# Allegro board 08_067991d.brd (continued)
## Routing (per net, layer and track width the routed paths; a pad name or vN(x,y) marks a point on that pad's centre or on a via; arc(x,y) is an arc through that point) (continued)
UNNAMED_2_AD243XW_I16_SWN: length 5.8
  TOP w0.254: R19.1 52.47,51.82 51.31,50.66 48.63,50.66 48.48,50.82 U11.39
UNNAMED_2_AD243XW_I16_SYNC: length 5.2
  TOP w0.178: R9.2 42.42,59.98 43.82,58.58 43.82,56.98 43.7,56.86 U11.8
UNNAMED_2_AD243XW_I16_VIN: length 7.5
  TOP w0.254: U11.46 48.98,54.32 v1(49.28,54.61)
  TOP w0.635: v1(49.28,54.61) 49.66,54.99 E3.2
  BOTTOM w0.305: v1(49.28,54.61) 49.24,54.61 48.48,53.85 48.25,53.85 C6.1
  BOTTOM w0.508: C7.1 v1(49.28,54.61)
UNNAMED_2_CAP_I61_N1: length 14.8
  TOP w0.508: R24.1 v1(58.29,60.8) ; v1(58.29,59.53) R27.1 ; v1(64.13,63.74) R22.1
  L3_PWR w0.508: v1(58.29,59.53) v1(58.29,60.8) 61.23,63.74 v1(64.13,63.74) 64.45,63.42 65.58,63.42 v1(66.93,64.77) v1(67.56,64.77)
UNNAMED_2_CN18PODDEVEN_I182_N1: length 2.6
  TOP w0.178: P2.1 E1.1
UNNAMED_2_CN18PODDEVEN_I182_N2: length 2.2
  TOP w0.178: P2.3 R1.1
UNNAMED_2_CN18PODDEVEN_I182_N3: length 2.2
  TOP w0.178: P2.5 R2.1
UNNAMED_2_CN18PODDEVEN_I182_N4: length 2.2
  TOP w0.178: P2.7 R3.1
UNNAMED_2_CN18PODDEVEN_I182_N5: length 2.2
  TOP w0.178: P2.9 R4.1
UNNAMED_2_CN18PODDEVEN_I182_N6: length 2.2
  TOP w0.178: P2.11 R5.1
UNNAMED_2_CN18PODDEVEN_I182_N7: length 2.2
  TOP w0.178: P2.13 R6.1
UNNAMED_2_CN18PODDEVEN_I182_N8: length 2.2
  TOP w0.178: P2.15 R7.1
UNNAMED_2_CN18PODDEVEN_I182_N9: length 2.2
  TOP w0.178: P2.17 R8.1
UNNAMED_2_DIOLED_I1_P: length 1.5
  TOP w0.178: R95.2 DS6.A
UNNAMED_2_DIOLED_I49_P: length 1.5
  TOP w0.178: R20.2 DS2.A
UNNAMED_2_DIOLED_I74_P: length 2.3
  TOP w0.178: DS3.A R21.2
UNNAMED_2_ICM24512_I59_E0: length 2.8
  TOP w0.178: R23.1 R22.2 U14.1
UNNAMED_2_ICM24512_I59_E1: length 3.5
  TOP w0.178: U14.2 R24.2 R25.1
UNNAMED_2_ICM24512_I59_E2: length 3.4
  TOP w0.178: R28.1 R27.2 U14.3
UNNAMED_2_ICM24512_I59_SCL: length 18
  TOP w0.178: S1.1B v1(79.25,55.13) ; U14.6 v1(65.89,59.53)
  BOTTOM w0.178: v1(79.25,55.13) 76.06,55.13 73.91,57.28 68.14,57.28 v1(65.89,59.53)
UNNAMED_2_ICM24512_I59_SDA: length 18.5
  TOP w0.178: U14.5 v1(65.89,58.26) ; S1.3B v1(79.25,52.59)
  BOTTOM w0.178: v1(65.89,58.26) 68.27,55.88 73.15,55.88 76.44,52.59 v1(79.25,52.59)
UNNAMED_2_NCTESTPAD_I202_N1: length 1.8
  TOP w0.178: TP10.1 R87.2
UNNAMED_3_ADLT8606V2_I35_BST: length 1.5
  TOP w0.254: C114.1 81.8,38.74 U8.1
UNNAMED_3_ADLT8606V2_I35_INTVCC: length 5.5
  TOP w0.203: U8.5 v1(84.33,40.18) ; U8.3 82.8,39.41 83.06,39.16 83.06,38.65 C53.1 v1(84.33,38.27)
  BOTTOM w0.254: v1(84.33,40.18) v1(84.33,38.27)
UNNAMED_3_ADLT8606V2_I35_PG: length 2
  TOP w0.203: U8.8 82.8,45.47 R110.2
UNNAMED_3_ADLT8606V2_I35_RT: length 3
  TOP w0.203: R107.2 84.57,39.24 83.57,39.24 83.3,39.5 U8.4
UNNAMED_3_ADLT8606V2_I35_SW: length 4.9
  TOP w0.254: U8.2 82.3,39.3 82.45,39.16 82.45,37.92 82.25,37.73 C114.2
  TOP w0.508: C114.2 79.93,37.73 L14.1
UNNAMED_3_ADLT8606V2_I35_TR: length 3.7
  TOP w0.203: C82.1 84.2,45.84 84.2,45.67 84,45.47 83.57,45.47 83.3,45.2 U8.7
UNNAMED_3_CAP_I7_N1: length 3.4
  TOP w0.241: FL1.1 32.65,30.88 32.65,31.74 C18.1 32.65,32.21 32.65,33.01 32.82,33.18 L1.2
UNNAMED_3_CAP_I8_N1: length 3.4
  TOP w0.241: FL1.2 32.24,30.88 32.24,31.74 C19.1 32.24,32.21 32.24,33.01 32.07,33.18 L2.2
UNNAMED_3_CAP_I12_N1: length 9
  TOP w0.178: R29.2 C20.2 v1(34.93,26.38) ; R30.1 C21.1 v1(29.96,26.38)
  BOTTOM w0.178: v1(29.96,26.38) 30.13,26.22 34.77,26.22 v1(34.93,26.38)
UNNAMED_3_CAP_I14_N1: length 4.5
  TOP w0.241: 32.24,25.16 32.24,24.71 C23.1 ; 32.24,25.16 R30.2 32.24,25.71 ; 32.24,25.16 32.24,25.71 ; FL1.3 32.24,27.23 32.24,25.71
UNNAMED_3_CAP_I14_N2: length 10.4
  TOP w0.241: P1.3 31.81,17.78 32.22,18.19 32.22,21.99 C23.2
  BOTTOM w0.965: L8.1 29.62,20.71 30.59,19.75 P1.3
UNNAMED_3_CAP_I15_N1: length 4.5
  TOP w0.241: 32.65,25.71 32.65,27.23 FL1.4 ; 32.65,25.71 32.65,25.16 ; 32.65,25.71 R29.1 32.65,25.16 ; 32.65,25.16 32.65,24.71 C22.1
UNNAMED_3_CAP_I15_N2: length 10.5
  TOP w0.241: P1.2 33.11,17.78 32.63,18.27 32.63,21.95 C22.2
  BOTTOM w0.965: L7.1 35.36,20.71 34.4,19.75 P1.2
UNNAMED_3_CAP_I32_N2: length 10.7
  BOTTOM w0.762: C123.2 24,14.35 25.65,12.7 P1.GND
UNNAMED_3_DIOLED_I23_P: length 18.5
  TOP w0.508: DS4.C v1(24.96,2) ; v1(41.85,2) DS8.A
  BOTTOM w0.508: v1(24.96,2) v1(41.85,2)
UNNAMED_3_DIOLED_I24_P: length 23.4
  TOP w0.508: DS4.A v1(21.53,2)
  BOTTOM w0.508: v1(21.53,2) 19.3,2 19.05,2.25 19.05,21.79 R91.1
UNNAMED_3_RES_I45_N2: length 3.3
  TOP w0.203: U8.6 83.8,44.81 83.95,44.96 85.1,44.96 R109.2 R108.2
UNNAMED_4_ADMAX17612X_I50_FLAGN: length 2.5
  TOP w0.203: R115.2 79.01,24.03 v1(79.01,24.26) U10.6
  BOTTOM w0.178: R117.1 79.01,23.9 v1(79.01,24.26)
UNNAMED_4_ADMAX17612X_I50_OVLO: length 5
  TOP w0.203: R113.1 77.34,29.55 77.54,29.76 79.54,29.76 79.75,29.55 R114.2 79.75,28.96 80.01,28.69 U10.3
UNNAMED_4_ADMAX17612X_I50_SETI: length 3.5
  TOP w0.203: U10.8 80.01,24.26 79.25,23.49 79.25,22.61 78.99,22.35 R116.2
UNNAMED_4_ADMAX17612X_I50_UVLO: length 6.8
  TOP w0.203: R111.1 77.34,31.04 77.54,31.24 79.54,31.24 79.75,31.04 R112.2 79.75,30.43 80.42,29.76 80.42,28.17 80.51,28.07 U10.2
UNNAMED_4_CAP_I2_N1: length 3.4
  TOP w0.241: FL2.2 56.75,30.88 56.75,31.74 C26.1 56.75,32.21 56.75,33.01 56.58,33.18 L3.2
UNNAMED_4_CAP_I3_N1: length 3.4
  TOP w0.241: L4.2 57.33,33.18 57.16,33.01 57.16,32.21 C27.1 57.16,31.74 57.16,30.88 FL2.1
UNNAMED_4_CAP_I12_N1: length 9
  TOP w0.178: v1(54.47,26.38) C28.2 R31.2 ; R32.1 C29.1 v1(59.44,26.38)
  BOTTOM w0.178: v1(54.47,26.38) 54.64,26.22 59.28,26.22 v1(59.44,26.38)
UNNAMED_4_CAP_I14_N1: length 4.5
  TOP w0.241: 57.16,25.16 57.16,25.71 ; 57.16,25.16 R32.2 57.16,25.71 ; 57.16,25.16 57.16,24.72 C24.1 ; 57.16,25.71 57.16,27.23 FL2.4
UNNAMED_4_CAP_I14_N2: length 14.1
  TOP w0.241: C24.2 57.16,21.96 57.16,16.13 57.62,15.67 58.63,15.67 58.88,15.92 P13.3
  BOTTOM w0.965: L12.1 60.51,18.78 P13.3
UNNAMED_4_CAP_I16_N1: length 4.5
  TOP w0.241: 56.75,25.71 56.75,27.23 FL2.3 ; 56.75,25.71 R31.1 56.75,25.16 ; 56.75,25.71 56.75,25.16 ; 56.75,25.16 56.75,24.7 C30.1
UNNAMED_4_CAP_I16_N2: length 18.2
  TOP w0.241: P13.2 56.75,15.01 56.75,21.98 C30.2
  BOTTOM w0.965: L11.1 53.4,15.01 P13.2
UNNAMED_4_DIOLED_I30_P: length 18.5
  TOP w0.508: DS9.C v1(69.85,2) ; v1(53.28,2) DS12.A
  BOTTOM w0.508: v1(69.85,2) v1(53.28,2)
UNNAMED_4_DIOLED_I31_P: length 24
  TOP w0.508: DS9.A v1(73.53,2)
  BOTTOM w0.508: v1(73.53,2) 73.15,2 72.64,2.51 72.64,20.57 71.3,21.92 R36.1
UNNAMED_4_DIOSCHOTTKY_I34_N: length 19.8
  TOP w0.254: U10.10 81.01,23.88
  TOP w1.016: 81.01,23.88 81.01,22.91 C117.2 80.96,21.59 79.31,19.94 75.18,19.94 73.79,21.34 TP11.1
  BOTTOM w0.508: TP11.1 R36.2
UNNAMED_4_RES_I22_N2: length 1.8
  BOTTOM w0.508: Q1.4 63.13,27.36 R33.2
UNNAMED_5_CAP_I15_N1: length 70.1
  TOP w0.178: E5.1 C37.2 v1(56.72,46.43) ; C39.1 v1(42.25,29.11) ; C36.2 v1(42.25,40.66) ; C38.2 v1(32.25,46.43)
  BOTTOM w0.178: v1(56.72,46.43) 55.93,46.43 55.83,46.53 v1(55.29,46.53) 54.43,46.53 v1(53.61,45.71) 53.98,45.35 53.98,43.56 49.91,39.5 49.91,36.71 46.86,33.67 46.86,29.97 46.1,29.21 v1(45.29,29.21) 44.58,29.21 43.76,28.39 v1(43.61,28.39) 42.98,28.39 v1(42.25,29.11) 42.25,30.82 47.05,35.62 47.05,38.54 46.74,38.86 45.62,38.86 44.1,37.34 43.05,37.34 42.67,37.72 42.67,39 v1(43.61,39.94) 42.89,40.66 v1(42.25,40.66) 38.08,40.66 36.32,42.42 33.02,42.42 31.5,43.94 31.5,46.1 31.83,46.43 v1(32.25,46.43) 32.89,46.43 v1(33.61,45.71)
UNNAMED_5_ICT3902_I1_DATA: length 2.8
  TOP w0.178: R40.1 v1(44,38.55)
  BOTTOM w0.178: v1(45.29,39.94) 44,38.65 v1(44,38.55)
UNNAMED_5_ICT3902_I2_DATA: length 3
  TOP w0.178: v1(44,27.13) R39.1
  BOTTOM w0.178: v1(45.29,28.39) 45.29,27.63 44.79,27.13 v1(44,27.13)
UNNAMED_5_ICT3902_I3_DATA: length 4.4
  TOP w0.178: v1(32.77,44.32) R38.1
  BOTTOM w0.203: v1(35.29,45.71) 35.29,45.07 34.8,44.58 33.02,44.58 v1(32.77,44.32)
UNNAMED_5_ICT3902_I4_DATA: length 2.6
  TOP w0.178: R37.1 v1(56.65,44.96)
  BOTTOM w0.178: v1(55.29,45.71) 56.04,44.96 v1(56.65,44.96)
UNNAMED_7_AD8606_I11_INV: length 10.9
  TOP w0.178: C52.P 17.5,66.27 18.61,67.37 18.61,72.58 C46.2 18.67,73.01 18.67,73.4 U7.A1 U7.B1
UNNAMED_7_AD8606_I11_NINV: length 2.4
  TOP w0.178: U7.C1 20.18,73.01 C44.1 20.42,72.75 R44.2
UNNAMED_7_AD8606_I21_INV: length 9
  TOP w0.178: U7.B3 U7.A3 18.85,74.91 18.67,75.09 18.67,75.82 C45.2 18.61,76.25 18.61,79.31 17.49,80.42 C51.P
UNNAMED_7_AD8606_I21_NINV: length 2.4
  TOP w0.178: U7.C3 20.18,75.81 C43.1 20.42,76.08 R43.2
UNNAMED_7_AD8606_I58_INV: length 10.9
  TOP w0.178: C62.P 17.5,89.13 18.61,90.23 18.61,95.44 C60.2 18.67,95.87 18.67,96.26 U9.A1 U9.B1
UNNAMED_7_AD8606_I58_NINV: length 2.4
  TOP w0.178: U9.C1 20.18,95.87 C58.1 20.42,95.61 R54.2
UNNAMED_7_AD8606_I66_INV: length 9
  TOP w0.178: U9.B3 U9.A3 18.85,97.77 18.67,97.95 18.67,98.68 C59.2 18.61,99.11 18.61,102.17 17.49,103.28 C61.P
UNNAMED_7_AD8606_I66_NINV: length 2.4
  TOP w0.178: U9.C3 20.18,98.67 C57.1 20.42,98.94 R53.2
UNNAMED_7_CAP_I20_N1: length 2.3
  TOP w0.178: R42.2 R44.1 C46.1
UNNAMED_7_CAP_I22_N1: length 2.3
  TOP w0.178: R41.2 R43.1 C45.1
UNNAMED_7_CAP_I29_N1: length 7.9
  TOP w0.178: C48.1 11.44,113.4 12.32,112.52 C50.2
  TOP w0.203: C48.1 E10.2
UNNAMED_7_CAP_I34_N1: length 9.1
  TOP w0.203: C49.2 13.58,128.75 12.33,127.51 12.33,126.24 11.29,125.19 C47.1 E9.2
UNNAMED_7_CAP_I38_N1: length 11.3
  TOP w0.178: R48.2 C55.1 R50.1 6.44,69.47 7.69,70.71 P6.2
UNNAMED_7_CAP_I46_N1: length 6.3
  TOP w0.178: P6.3 4.4,80 4.82,80.42 R49.1 C54.1 R47.2
UNNAMED_7_CAP_I60_N1: length 11.3
  TOP w0.178: P7.2 7.69,93.57 6.44,92.33 R58.1 C65.1 R56.2
UNNAMED_7_CAP_I64_N1: length 2.3
  TOP w0.178: C60.1 R54.1 R52.2
UNNAMED_7_CAP_I67_N1: length 2.3
  TOP w0.178: C59.1 R53.1 R51.2
UNNAMED_7_CAP_I73_N1: length 6.3
  TOP w0.178: R55.2 C64.1 R57.1 4.82,103.28 4.4,102.86 P7.3
UNNAMED_7_CAP_I83_N1: length 3.5
  TOP w0.178: R45.1 23.44,128.19 22.89,128.75 C49.1
UNNAMED_7_CAP_I84_N1: length 3.4
  TOP w0.178: R46.1 23.44,113.23 22.73,112.52 C50.1
UNNAMED_7_CAPP_I23_N2: length 2.4
  TOP w0.178: R48.1 C52.N
UNNAMED_7_CAPP_I25_N2: length 2.5
  TOP w0.178: R47.1 C51.N
UNNAMED_7_CAPP_I68_N2: length 2.4
  TOP w0.178: R56.1 C62.N
UNNAMED_7_CAPP_I69_N2: length 2.5
  TOP w0.178: R55.1 C61.N
UNNAMED_7_CN3P_I18_N2: length 2.9
  TOP w0.203: E10.1 9.86,116.94 P4.2
UNNAMED_7_CN3P_I18_N3: length 2.9
  TOP w0.203: P4.3 5.26,125.19 E9.1
UNNAMED_10_CAP_I3_N1: length 11.4
  TOP w1.016: L5.2 C75.1 P16.1
UNNAMED_10_CAP_I5_N1: length 1.3
  TOP w0.508: 44.07,113.6 45.32,113.6 C68.1
UNNAMED_10_CAP_I7_N1: length 1.5
  TOP w0.508: R61.2 C69.1
UNNAMED_10_CAP_I9_N2: length 11.4
  TOP w1.016: P17.1 C76.2 L6.2
UNNAMED_10_CAP_I12_N1: length 4.7
  TOP w0.254: U16.16 52.07,119.48 53.21,120.61 C79.1
UNNAMED_10_CAP_I14_N1: length 11.4
  TOP w1.016: L9.2 C77.1 P18.1
UNNAMED_10_CAP_I15_N2: length 11.4
  TOP w1.016: P19.1 C78.2 L10.2
UNNAMED_10_CAP_I19_N2: length 4.6
  TOP w0.254: 49.4,115.74 U16.19
  TOP w0.508: C70.2 47.86,115.74 49.4,115.74
  TOP w0.635: C70.2 R61.1
UNNAMED_10_CAP_I21_N1: length 2.8
  TOP w0.254: U16.22 48.42,114.24 C31.1
UNNAMED_10_CAP_I21_N2: length 10.2
  TOP w0.254: U16.23 50.05,113.74 49.74,113.43 49.74,112.65
  TOP w0.406: 49.74,112.65 49.4,112.31 49.4,111.52 48.72,110.84 C31.2
  TOP w0.508: C31.2 45.03,110.84 L5.1 ; C68.2 45.34,111.38
UNNAMED_10_CAP_I24_N2: length 5
  TOP w0.254: C73.2 51.18,120.78 51.57,120.38 U16.17
UNNAMED_10_CAP_I25_N1: length 1.4
  TOP w0.508: R62.2 C71.1
UNNAMED_10_CAP_I26_N2: length 3.2
  TOP w0.254: 54.99,115.74 U16.12
  TOP w0.508: C67.2 56.97,115.74 54.99,115.74
UNNAMED_10_CAP_I29_N1: length 10.6
  TOP w0.254: L10.1 61.09,109.34 R76.1 57.66,110.61 C34.1 ; 55.05,113.54 54.85,113.74 U16.8
  TOP w0.508: C34.1 56.52,110.99 55.24,112.27 55.24,113.34 55.05,113.54
UNNAMED_10_CAP_I29_N2: length 3.2
  TOP w0.178: 55.37,114.22 55.36,114.24 U16.9
  TOP w0.508: 55.37,114.22 56.91,114.22 C34.2
UNNAMED_10_CAP_I39_N1: length 1.3
  TOP w0.508: C72.1 R76.2
UNNAMED_10_CAP_I55_N1: length 3.3
  TOP w0.178: U16.6 53.57,112.23 v1(53.95,111.86)
  BOTTOM w0.178: R99.2 C118.1 54.36,111.45 v1(53.95,111.86)
UNNAMED_10_CN3P_I53_N2: length 13
  TOP w0.178: R63.2 48.77,106.3 50.04,107.57 53.06,107.57 53.98,108.49 53.98,111.06 53.07,111.96 U16.5
  TOP w0.254: R63.2 JP2.2
UNNAMED_10_CN3P_I54_N1: length 2.3
  TOP w0.254: R65.2 54.74,106.15 JP3.1
UNNAMED_10_CN3P_I54_N2: length 5.8
  TOP w0.178: R66.1 55.47,108.34 57.28,106.53 JP3.2
UNNAMED_10_DIOLED_I30_N: length 15.2
  TOP w0.178: DS11.C 47.5,99.42 47.5,107.44 50.04,109.98 50.13,110.07 50.13,111.99 50.44,112.31 U16.24
UNNAMED_10_DIOLED_I30_P: length 1.5
  TOP w0.178: DS11.A R64.2
UNNAMED_10_ICBD28623MUV_I28_BCLK: length 1.9
  TOP w0.178: R68.2 U16.3
UNNAMED_10_ICBD28623MUV_I28_LRCLK: length 2.1
  TOP w0.178: R59.2 52.57,111.36 U16.4
UNNAMED_10_ICBD28623MUV_I28_MUTEX: length 4.2
  TOP w0.178: R66.2 54.49,109.71 54.49,113.06 54.32,113.24 U16.7
UNNAMED_10_ICBD28623MUV_I28_SDATA: length 2.1
  TOP w0.178: U16.2 51.57,111.37 R67.2
UNNAMED_11_ADAU1701_I48_ADCRES: length 2
  TOP w0.178: U12.3 R69.2
UNNAMED_11_ADAU1701_I48_CM: length 2.9
  TOP w0.254: U12.40 39.39,83.03 C89.1 C91.1
UNNAMED_11_ADAU1701_I48_DVDD: length 4.8
  TOP w0.254: C96.1 50.61,84.53 U12.24 ; U12.13 C94.1
  TOP w0.508: C94.1 v1(51.55,79.03) ; C96.1 v1(51.55,84.72)
  vias: v1(51.18,74.92) v1(51.18,74.41) v1(51.18,73.9) v1(51.69,74.92) v1(51.69,74.41) v1(51.69,73.9) v1(54.86,83.44) v1(55.37,83.44)
UNNAMED_11_ADAU1701_I48_FILTA: length 3.9
  TOP w0.178: v1(38.99,79.38) 39.14,79.53 U12.47
  BOTTOM w0.178: C85.1 C87.1 39,79.38 v1(38.99,79.38)
UNNAMED_11_ADAU1701_I48_FILTD: length 2.9
  TOP w0.254: C98.1 C99.1 39.36,82.53 U12.41
UNNAMED_11_ADAU1701_I48_MP6: length 3.9
  TOP w0.178: R70.2 51.81,80.52 50.55,80.52 50.06,80.03 U12.15
UNNAMED_11_ADAU1701_I48_PLLLF: length 4.8
  TOP w0.178: U12.35 C97.1 C95.1
UNNAMED_11_ADAU1701_I48_RESETB: length 21.3
  TOP w0.178: U12.5 44.24,76.61 44.2,76.56 44.2,75.04 44.44,74.8 45.12,74.8 45.3,74.61 C80.2 45.3,72.82 R98.1 45.6,71.87 45.83,71.64 49.03,71.64 49.53,72.14 56.26,72.14 56.77,71.63 56.77,70.87 57.53,70.1 R88.1
UNNAMED_11_ADAU1701_I48_SELFBOOT: length 9.9
  TOP w0.178: U12.6 v1(44.74,75.69) ; R73.1 P9.1
  BOTTOM w0.178: v1(44.74,75.69) 42.46,73.41 P9.1
UNNAMED_11_ADAU1701_I48_VDRIVE: length 5.4
  TOP w0.254: U12.17 R72.1 53.19,81.03 Q2.1
UNNAMED_11_CAP_I20_N2: length 1
  TOP w0.178: R71.1 C95.2
UNNAMED_11_CAP_I41_N2: length 2.8
  TOP w0.508: E11.2 C100.2 U15.8
UNNAMED_11_CN10P_I109_N4: length 4.6
  TOP w0.178: DS5.A 67.56,93.68 P10.4
UNNAMED_11_DIOLED_I121_N: length 2.2
  TOP w0.178: R77.1 DS5.C
UNNAMED_11_ICM24512_I37_SCL: length 2
  TOP w0.178: U15.6 R74.1
UNNAMED_11_ICM24512_I37_SDA: length 2
  TOP w0.178: U15.5 R75.1
UNNAMED_11_NCTESTPAD_I134_N1: length 1.8
  TOP w0.178: TP12.1 R88.2
UNNAMED_12_ADLT8609_I124_BST: length 2.2
  TOP w0.178: C105.2 15.49,51.44 15.31,51.27 U5.1
UNNAMED_12_ADLT8609_I124_EN: length 2.8
  TOP w0.178: R80.1 R79.1 15.22,45.92 14.72,46.42 U5.10
UNNAMED_12_ADLT8609_I124_FB: length 4
  TOP w0.178: R84.2 C107.2 R85.2 11.84,46.74 12.15,47.05 U5.6
UNNAMED_12_ADLT8609_I124_INTVCC: length 5.3
  TOP w0.178: 10.15,52.27 10.13,52.27 C103.1 9.84,52.58 10.15,52.27 ; 10.15,52.27 R81.1 13.39,52.27 13.72,51.94 U5.3
UNNAMED_12_ADLT8609_I124_PG: length 4.5
  TOP w0.178: R83.2 12.32,43.94 13.46,45.09 13.46,45.85 13.72,46.1 U5.8
UNNAMED_12_ADLT8609_I124_RT: length 4.5
  TOP w0.178: R82.1 10.15,50.58 10.33,50.4 13.04,50.4 13.22,50.58 U5.4
UNNAMED_12_ADLT8609_I124_SYNC: length 1.5
  TOP w0.178: U5.5 R81.2
UNNAMED_12_ADLT8609_I124_TR: length 2.6
  TOP w0.178: C104.2 12.42,45.34 13.22,46.14 U5.7
UNNAMED_12_ADLT8609_I124_VIN: length 2.9
  TOP w0.508: E14.1 12.23,37.07 R151.1
UNNAMED_12_CAP_I111_N1: length 14.5
  TOP w0.508: C107.1 v1(8.28,46.74) ; R84.1 v1(8.28,47.88)
  BOTTOM w0.508: v1(8.28,46.74) v1(8.28,47.88) 11.81,51.41 v1(11.81,57.66) v1(11.81,58.29)
UNNAMED_12_DIOLED_I105_P: length 1.5
  TOP w0.508: DS1.A R16.2
UNNAMED_12_DIOLED_I136_P: length 1.7
  TOP w0.508: DS10.A R151.2
VOUT0: length 21.1
  TOP w0.178: R41.1 25.91,78.36 27.54,79.99 40.24,79.99 40.28,80.03 U12.46
VOUT1: length 27.6
  TOP w0.178: R42.1 28.32,70.48 34.04,76.2 39.24,76.2 41.91,78.87 41.91,80.39 41.77,80.53 U12.45
VOUT2: length 46.9
  TOP w0.178: R51.1 v1(21.21,101.22) ; v1(42.93,81.28) 42.67,81.03 U12.44
  BOTTOM w0.178: v1(42.93,81.28) 42.58,80.94 41.74,80.94 41.27,81.41 37.85,81.41 37.21,80.77 21.46,80.77 19.69,82.55 19.69,99.69 v1(21.21,101.22)
VOUT3: length 33.4
  TOP w0.178: R52.1 v1(21.21,93.34) ; v1(42.29,81.66) 42.29,81.66 42.16,81.53 U12.43
  BOTTOM w0.178: v1(21.21,93.34) 21.21,84.58 23.75,82.04 41.4,82.04 41.78,81.66 v1(42.29,81.66)
VSENSEP: length 40.5
  TOP w0.254: U11.40 48.63,51.32 48.78,51.17 50.4,51.17 v1(51.56,52.32)
  BOTTOM w0.406: v1(51.56,52.32) 59.94,52.32 69.22,43.05 69.22,28.61 R34.1

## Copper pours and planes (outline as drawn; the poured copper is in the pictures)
24V on TOP (solid shape): 71.89,30.98 71.89,27.06 71.2,26.37 67.68,26.37 67.68,31.96 70.91,31.96
24V on TOP (solid shape): 82.55,49.91 82.55,45.64 82.52,45.59 81.41,45.59 81.41,49.91 81.53,50.04 82.42,50.04
24V on TOP: 24.93,31.96 24.93,26.37 21.65,26.37 20.45,27.57 20.45,30.99 21.42,31.96
24V on BOTTOM: 66.73,34.47 66.73,35.87 69.22,35.87 69.22,34.01 67.76,34.01 67.76,34.47
24V on BOTTOM: 45.78,112.39 55.79,112.39 57.06,111.12 59.86,111.12 59.86,122.14 56.48,122.14 51.82,117.47 45.78,117.47
24V on BOTTOM: 39.15,25.93 23.37,25.93 22.49,26.81 18.04,26.81 17.91,26.67 17.91,24.07 25.39,24.07 25.74,23.72 39.15,23.72
24V on L4_PWR: 25.72,138.43 87.63,138.43 87.63,1.27 1.27,1.27 1.27,40.83 25.97,40.83 25.97,16.64 26.06,16.41 26.29,16.32 69.6,16.32 69.82,16.41 69.91,16.64 69.91,23.11 69.82,23.34 69.6,23.43 62.67,23.43 62.67,35.5 76.33,35.5 76.55,35.59 76.64,35.81 76.64,77.6 76.55,77.82 76.33,77.91 60.77,77.91 60.77,93.73 60.68,93.95 60.45,94.04 58.61,94.04 58.61,108.33 58.52,108.56 58.29,108.65 44.32,108.65 44.1,108.56 44.01,108.33 44.01,98.23 39.75,98.23 39.63,98.21 39.53,98.14 35.3,93.92 25.72,93.92 ; 3 cut-outs
DGND on TOP: 10.33,43.17 7.86,43.17 7.62,42.93 7.62,41.4 7.87,41.15 10.31,41.15 10.33,41.16
DGND on TOP: 1.27,138.43 87.63,138.43 87.63,1.27 1.27,1.27 ; 14 cut-outs
DGND on BOTTOM: 1.27,138.43 87.63,138.43 87.63,1.27 1.27,1.27 ; 17 cut-outs
DGND on L2_GND, L5_GND: 1.27,138.43 87.63,138.43 87.63,1.27 1.27,1.27 ; 4 cut-outs
DGND on L3_PWR: 1.27,138.43 87.63,138.43 87.63,1.27 1.27,1.27 ; 15 cut-outs
DGND on L4_PWR: 1.27,138.43 25.08,138.43 25.08,104.71 1.27,104.71 ; 1 cut-out
DGND on L4_PWR: 41.59,55.44 47.56,55.44 47.56,54.48 47.57,54.42 47.59,54.36 47.57,54.29 47.56,54.23 47.56,49.59 41.59,49.59
VDD_3V3 on TOP: 10.22,59.8 11.37,59.8 11.58,60.02 16.64,60.02 16.64,62.1 16,62.74 10.55,62.74 10.5,62.69 10.5,61.94 10.22,61.66
VDD_3V3 on TOP: 56.57,80.73 56.57,78.61 56.44,78.49 55.68,78.49 55.55,78.61 55.55,80.73
VDD_3V3 on TOP: 35.81,86.83 39.33,86.83 39.5,87 39.5,88.27 39.33,88.43 35.81,88.43
VDD_3V3 on BOTTOM: 66.04,21.33 66.04,19.81 67.95,19.81 68.07,19.94 68.07,21.21 67.95,21.33
VDD_3V3 on L4_PWR: 44.64,108.01 57.98,108.01 57.98,93.73 58.07,93.5 58.29,93.41 60.13,93.41 60.13,77.6 60.23,77.37 60.45,77.28 76.01,77.28 76.01,36.13 62.36,36.13 62.13,36.04 62.04,35.81 62.04,23.11 62.13,22.89 62.36,22.8 69.28,22.8 69.28,16.95 26.61,16.95 26.61,41.15 26.51,41.37 26.29,41.47 1.27,41.47 1.27,104.08 25.08,104.08 25.08,93.6 25.18,93.37 25.4,93.28 35.43,93.28 35.55,93.31 35.66,93.37 39.88,97.6 44.32,97.6 44.55,97.69 44.64,97.92 ; 1 cut-out
VDD_5V on TOP (solid shape): 78.05,33.1 77.85,32.89 76.58,32.89 76.33,33.15 76.33,39.32 76.58,39.57 78.05,39.57
VDD_5V on TOP: 81.79,29.72 81.46,29.72 81.28,29.54 81.28,28.52 81.13,28.37 80.9,28.37 80.72,28.55 80.72,30.78 80.82,30.89 81.84,30.89 81.94,30.78 81.94,29.87
VDD_5V on TOP: 53.67,54.46 55.17,54.46 55.27,54.56 55.27,55.4 55.17,55.5 53.67,55.5
(no net) on TOP: 67.68,31.96 67.68,26.37 71.2,26.37 71.89,27.06 71.89,30.98 70.91,31.96
(no net) on TOP: 78.05,39.57 76.58,39.57 76.33,39.32 76.33,33.15 76.58,32.89 77.85,32.89 78.05,33.1
(no net) on TOP: 80.85,37.41 80.42,36.98 80.42,35.86 79.43,35.86 79.43,39.57 80.42,39.57 80.42,38.43 80.82,38.02 82.12,38.02 82.32,38.23 82.32,39.4 82.4,39.4 82.73,39.07 82.73,37.72 82.42,37.41
(no net) on TOP: 82.55,45.59 82.55,49.91 82.42,50.04 81.53,50.04 81.41,49.91 81.41,45.59
AD243X_IOVDD on TOP: 54.62,88.43 51.09,88.43 50.93,88.27 50.93,87 51.09,86.83 54.62,86.83
AD243X_IOVDD on L3_PWR: 52.7,88.39 52.45,88.65 51.05,88.65 50.8,88.39 50.8,81.79 51.05,81.53 52.45,81.53 52.7,81.79
AD243X_IOVDD on L4_PWR: 45.47,88.96 52.26,88.96 52.26,86.8 46.99,86.8 46.77,86.71 46.67,86.49 46.67,73.28 46.77,73.05 46.99,72.96 54.17,72.96 54.17,65.09 42.67,65.09 42.45,64.99 42.35,64.77 42.35,60.71 42.45,60.48 42.67,60.39 44.13,60.39 44.13,56.07 41.27,56.07 41.05,55.98 40.96,55.75 40.96,49.59 30.54,49.59 30.54,63.18 33.59,63.18 33.59,60.71 33.68,60.48 33.91,60.39 36.32,60.39 36.55,60.48 36.64,60.71 36.64,71.06 43.81,71.06 44.04,71.15 44.13,71.37 44.13,73.79 44.11,73.91 44.04,74.01 43.12,74.93 43.12,86.61
AD243X_VOUT2 on TOP: 68.57,65.15 70.37,65.15 70.48,65.27 70.48,66.16 70.36,66.28 68.71,66.28 68.57,66.14
AD243X_VOUT2 on TOP: 45.34,44.43 45.47,44.83 45.38,45.32 45.38,45.68 45.02,46.04 45.02,47.46 44.85,47.63 44.85,49.01 44.55,49.01 44.55,47.63 44.39,47.47 44.39,46.04 43.93,45.59 43.93,45.07 43.81,44.83 44,44.43 44,43.63 44.2,43.43 45.21,43.43 45.34,43.56
AD243X_VOUT2 on L4_PWR: 42.99,64.45 55.69,64.45 55.69,43.24 41.59,43.24 41.59,48.96 47.88,48.96 48.1,49.05 48.2,49.28 48.2,54.17 53.47,54.17 53.69,54.26 53.78,54.48 53.78,60.71 53.69,60.93 53.47,61.02 42.99,61.02
ISENSEP on BOTTOM: 64.83,35.87 64.83,34.33 64.2,33.71 63.2,33.71 63.2,32.69 63.35,32.69 63.35,32.39 62.62,32.39 62.62,31.8 63.35,31.8 63.35,29.97 62.62,29.97 62.62,29.36 63.35,29.36 63.35,29.19 67.47,29.19 67.47,29.36 68.2,29.36 68.2,29.97 67.47,29.97 67.47,31.8 68.2,31.8 68.2,32.39 67.47,32.39 67.47,32.69 67.62,32.69 67.62,33.71 66.35,33.71 66.35,33.72 65.87,34.2 65.87,35.87
UNNAMED_2_AD243XW_I16_DVDD1 on L4_PWR: 44.77,60.39 53.15,60.39 53.15,54.8 48.2,54.8 48.2,55.75 48.1,55.98 47.88,56.07 44.77,56.07
UNNAMED_2_CAP_I61_N1 on TOP: 67.91,66.14 66.92,66.14 66.42,65.65 66.42,61.84 68.45,61.84 68.45,62.22 67.91,62.77
UNNAMED_3_ADLT8606V2_I35_SW on TOP (solid shape): 80.42,38.43 80.82,38.02 82.12,38.02 82.32,38.23 82.32,38.44 82.32,39.02 82.32,39.03 82.32,39.4 82.4,39.4 82.55,39.24 82.57,39.22 82.59,39.2 82.73,39.06 82.73,37.72 82.42,37.41 80.85,37.41 80.42,36.98 80.42,35.86 79.43,35.86 79.43,39.57 80.42,39.57
UNNAMED_4_DIOSCHOTTKY_I34_N on BOTTOM: 64.47,26.44 62.82,26.44 62.31,25.93 50.25,25.93 50.25,23.72 71.22,23.72 71.51,24 71.51,27.68 67.62,27.68 67.62,28.37 64.47,28.37
UNNAMED_4_DIOSCHOTTKY_I34_P on BOTTOM: 64.68,22.61 67.42,22.61 67.42,21.7 66.15,21.7 65.87,21.42 64.68,21.42
UNNAMED_10_CAP_I3_N1 on TOP: 32.83,94.83 38.57,100.57 37.65,103.69 35.18,105.81 35.18,106.92 35.81,107.56 37.21,107.56 37.21,111.5 33.02,111.5 32.18,110.66 32.18,107.52 30.48,105.81 28.01,103.69 27.09,100.57
UNNAMED_10_CAP_I9_N2 on TOP: 32.83,133 38.57,127.25 37.65,124.13 35.18,122.01 35.18,120.9 35.81,120.27 37.21,120.27 37.21,116.33 33.02,116.33 32.18,117.17 32.18,120.31 30.48,122.01 28.01,124.13 27.09,127.25
UNNAMED_10_CAP_I14_N1 on TOP: 73.09,133 67.35,127.25 68.27,124.13 70.74,122.01 70.74,120.9 70.1,120.27 68.71,120.27 68.71,116.33 72.9,116.33 73.74,117.17 73.74,120.31 75.44,122.01 77.91,124.13 78.83,127.25
UNNAMED_10_CAP_I15_N2 on TOP: 73.09,94.83 67.35,100.57 68.27,103.69 70.74,105.81 70.74,106.92 70.1,107.56 68.71,107.56 68.71,111.5 72.9,111.5 73.74,110.66 73.74,107.52 75.44,105.81 77.91,103.69 78.83,100.57
UNNAMED_10_CAP_I19_N1 on TOP: 46.85,118.28 48.47,118.28 50.04,116.71 50.04,116.14 51.21,116.14 51.21,118.08 49.87,119.42 46.85,119.42
UNNAMED_10_CAP_I19_N2 on TOP: 48.65,116.42 46.85,116.42 46.6,116.17 45,116.17 44.55,116.62 44.55,120.27 42.04,120.27 42.04,115.57 42.33,115.28 48.65,115.28
UNNAMED_10_CAP_I21_N2 on TOP: 42.52,107.94 42.52,111.48 42.8,111.76 49.28,111.76 49.28,110.11 45.59,110.11 44.55,109.06 44.55,107.94
UNNAMED_10_CAP_I25_N2 on TOP: 58.52,118.22 56.12,118.22 54.61,116.71 54.61,116.14 53.43,116.14 53.43,118.08 54.95,119.59 58.67,119.59 58.97,119.89 63.4,119.89 63.4,117.09 61.37,117.09 61.17,117.29 59.45,117.29
UNNAMED_10_CAP_I29_N1 on TOP: 63.4,110.73 60.72,110.73 60.52,110.93 58.99,110.93 58.24,111.68 55.88,111.68 55.88,109.6 57.54,107.94 63.4,107.94
UNNAMED_11_ADAU1701_I48_DVDD on TOP: 54.62,75.22 51.09,75.22 50.93,75.06 50.93,73.79 51.09,73.62 54.62,73.62
UNNAMED_11_ADAU1701_I48_DVDD on TOP: 54.61,81.57 54.61,83.69 54.74,83.82 55.5,83.82 55.63,83.69 55.63,81.57
UNNAMED_11_ADAU1701_I48_DVDD on L4_PWR: 47.31,86.17 56.45,86.17 56.45,83.12 50.16,83.12 49.94,83.03 49.85,82.8 49.85,79.76 49.94,79.53 50.16,79.44 54.17,79.44 54.17,73.6 47.31,73.6
UNNAMED_12_ADLT8609_I124_SW on TOP: 14.37,50.69 14.37,51.94 14.78,52.35 14.78,53.16 15.71,54.09 16.34,54.09 16.34,55.05 12.63,55.05 12.63,53.79 14.06,52.36 14.06,50.69
UNNAMED_12_ADLT8609_I124_VIN on TOP: 14.06,47.62 14.06,46 13.84,45.78 13.84,44.58 12.81,43.55 11.52,43.55 11.52,40.61 11.76,40.37 11.76,39.04 11.94,38.86 13.34,38.86 13.46,38.99 13.46,42.55 14.1,43.18 14.78,43.18 14.78,44.85 14.53,45.1 14.53,46.05 14.37,46.21 14.37,47.62
UNNAMED_12_CAP_I111_N1 on TOP: 12.63,56.45 16.34,56.45 16.34,57.42 14.45,57.42 13.45,58.42 13.45,59.36 12.46,59.36 12.29,59.19 10.22,59.19 9.99,58.97 9.99,55.63 11.81,55.63

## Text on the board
Ref Des/Silkscreen Bottom: A | C
User.Comments: SEE NOTE 6 | (4 PLACES) | 5.    U11 IS A DEVICE-SOCKET COMBO AND FOLLOWS THIS SOLDERPASTE INSTRUCTION: | 6.    BOARD ASSEMBLY SPECIAL NOTES: (IN ORDER TO MINIMIZE MIC DEVICES (U1-U4) DAMAGE) | 7.    BOARDS TO BE SHIPPED SINGULATED AFTER ASSEMBLY PROCESS. | SMOOTHEN EDGES AND FREE FROM BURRS AFTER DEPANELIZATION PROCESS. | A. DO NOT BOARD WASH OR CLEAN AFTER THE REFLOW PROCESS. | C. DO NOT DIRECTLY EXPOSE TO ULTRASONIC PROCESSING, WELDING, OR CLEANING. | E. DO NOT APPLY OVER 30 PSI OF AIR PRESSURE INTO THE PORT HOLE. | B. DO NOT BRUSH BOARD WITH OR WITHOUT SOLVENTS AFTER THE REFLOW PROCESS. | D. DO NOT INSERT ANY OBJECT IN PORT HOLE OF DEVICE AT ANY TIME. | F. DO NOT PULL A VACUUM OVER PORT HOLE OF THE MICROPHONE. | G. DO NOT APPLY A VACUUM WHEN REPACKING INTO SEALED BAGS AT A RATE | SUPPLIED PART | U11(DEVICE) | U11(SOCKET) | FASTER THAN 0.5 ATM/SEC. | INSTALLED SOCKET | INSTALLED PART | INSTALLED DUT | NO PASTEMASK | PASTEMASK
Ref Des/Assembly Top: 1 | C | A | MATE ENTRY | +
Ref Des/Silkscreen Top: 24V | C | A | 3V3 | GND | MISO | MOSI | SCK | SIO2 | ADR1 | MCLK | AD2437 SIO0 SEL | IRQ | MULTIPURPOSE | SPKR L | SPKR- | (MP 1,2,3,7,8,9) | 2 | MAX LOAD: | 8 OHMS | BOOT | DISABLE | PINS | PORT A | TOWARDS MAIN | ERROR | GAIN | EVAL-AD2437B1NZ | MUTE | RESET | SI02 | PORT B | TOWARDS SUB | I2C BUS SEL | SPKR R | SPKR R- | USBi | DAC1 OUT | DAC0 OUT | ADC IN | PDM_OUT2 | AD_DRX0 | ADA_DRX0 | I2S | CONNECTOR | BCLK | SYNC | SIO4 | SIO3 | MALE | SIO0 | SIO1 | PDM_CLK | FEMALE | +
PAGE_OUTLINE: B | C | D | CHANGES PER ECR-106613 | CHANGES PER ECR-110081 | CHANGES PER ECR-113667 | 21MAR22 | 29NOV22 | 03APR23 | K. GAGNE | R. WHITNEY | CUSTOMER EVALUATION Z
DIMENSION: - | " " | (REF) | +2/-0 | DIA MAX
User.11: C | A | 1 | SECONDARY SIDE | PRIMARY SIDE | SEE DETAIL X | (4 PLACES)
User.12: A | C
User.15: 15.    BOARDS TO BE SHIPPED IN ARRAY AND KEEP INTACT. | PANEL TO BE SUBJECTED TO CUSTOMER'S APPROVAL. | PANELED SOLDER PASTE STENCIL SHOULD BE SENT TO THE CUSTOMER. | 32 MILS 370HR | 5 MILS 370HR | NOTE: ALL IMPEDANCE TOLERANCE +/-10% | LAYER | L1 | L3 | L6 | 100 OHMS DP | 50 OHMS SE | IMPEDANCE | SE = SINGLE ENDED | DP = DIFFERENTIAL PAIR | REFERENCE | L5 | L2 | LINE WIDTH | 9.5 MILS | 7 MILS | 6.5 MILS | SPACE | N/A | IMPEDANCE TABLE
User.24: 08-      -07 | L2 GND
User.25: 08-      -08 | L3 PWR
User.26: 08-      -09 | L4 PWR
User.27: 08-      -10 | L5 GND
User.45: FIGURE | SIZE | 10.0 | 40.0 | 45.0 | 50.0 | 65.0 | 250.0 | 20.0 | 33.0 | 63.0 | 67.0 | 125.0 | PLATED | NON-PLATED | DRILL CHART :TOP to BOTTOM | ALL UNITS ARE IN MILS | QTY | 1313 | 10 | 65 | 4 | 2 | TOLERANCE/NOTES
